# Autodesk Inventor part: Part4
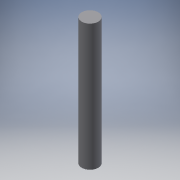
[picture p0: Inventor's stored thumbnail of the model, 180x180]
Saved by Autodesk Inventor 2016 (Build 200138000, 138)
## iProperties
Created: 2020-04
Part Number: Part4
Material: Generic
Document SubType Name: Modeling
Designer: merlin
Density: 1 g/cm^3
Appearance: Default
Author: merlin
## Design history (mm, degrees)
sketch "Sketch1"
  geometry: C1 r 3.81 at (225.425, 34.925); 1 further point
  constraints: 1 centre point
  dimensions: "d0" = 7.62 dimension on point (0, 0) C1.centre C1; "d0" = 7.62 diameter of C1
extrude "Extrusion1" new body sketch "Sketch1" distance "d1" = 58.42; taper "d2" = 0 deg
body "Solid1"
